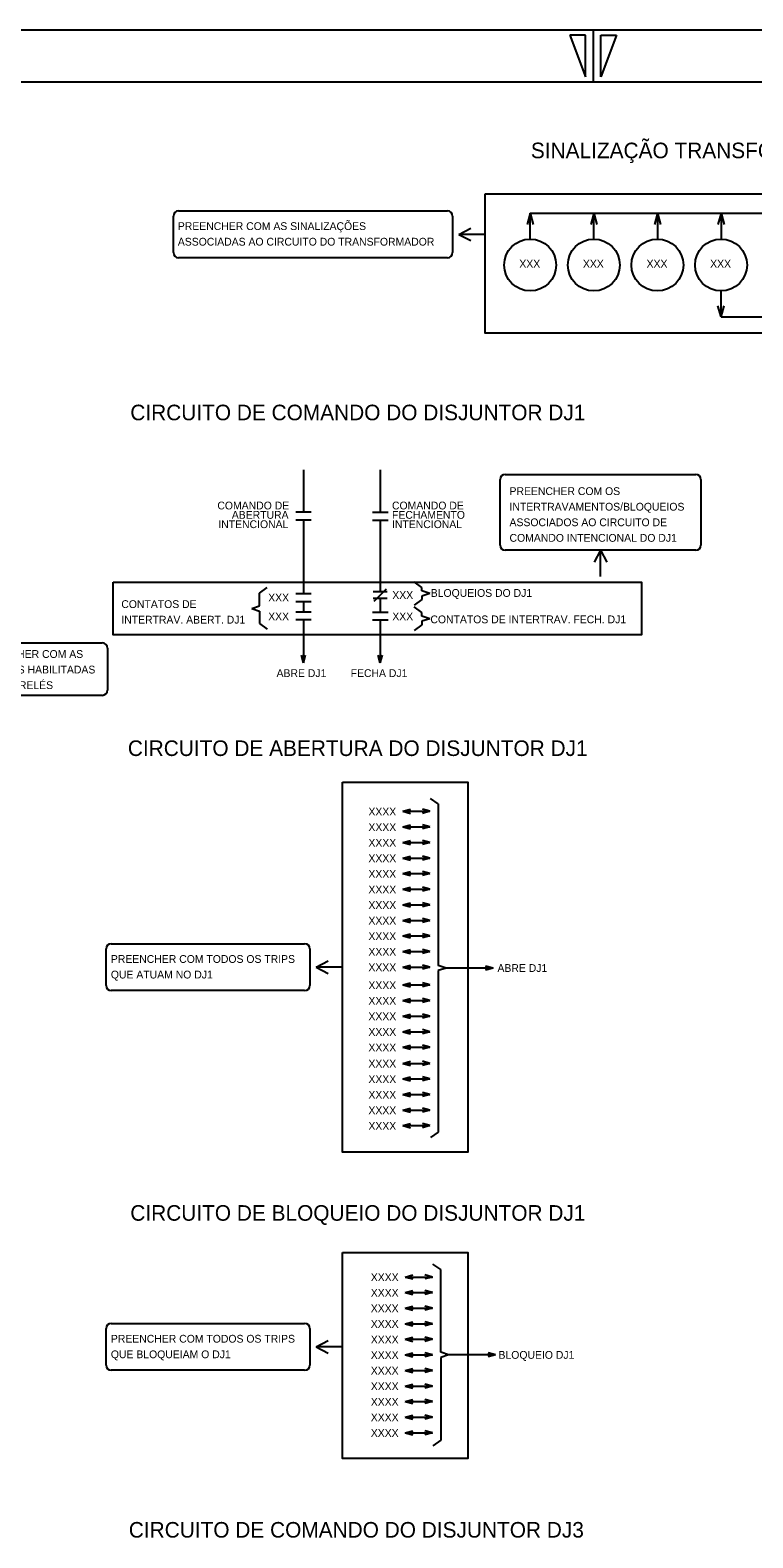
# Model space of a CAD drawing. Extents: x 501 to 1404, y 358 to 952.
# Drawn here: x 1110.2 to 1249.3, y 661.6 to 952 of the extents above; entities that cross this region are included whole.
import ezdxf

# ---------------------------------------------------------------- set-up
doc = ezdxf.new("R2010")
doc.units = 0
doc.layers.add('New Level (0)', color=7, linetype='Continuous')

# ---------------------------------------------------------------- blocks, each defined once
blk = doc.blocks.new('39')
for p, q in [((0, 0), (1.45, 0.39)), ((0, 0), (5.22, 0)), ((0, 0), (1.45, -0.39)), ((5.22, 0), (3.77, 0.39)), ((5.22, 0), (3.77, -0.39))]:
    blk.add_line(p, q)

msp = doc.modelspace()

# ---------------------------------------------------------------- linework, layer by layer
for p, q in [((1206.46, 916.72), (1205.87, 914.55)), ((1206.46, 911.72), (1206.46, 916.72)), ((1206.46, 916.72), (1265.58, 916.72)), ((1206.46, 916.72), (1207.04, 914.55)), ((1218.7, 916.72), (1218.12, 914.55)), ((1218.7, 911.72), (1218.7, 916.72)), ((1218.7, 916.72), (1219.28, 914.55)), ((1230.94, 916.72), (1230.36, 914.55)), ((1230.94, 916.72), (1230.94, 911.72)), ((1230.94, 916.72), (1231.53, 914.55)), ((1243.19, 916.72), (1242.6, 914.55)), ((1243.19, 916.72), (1243.19, 911.72)), ((1243.19, 916.72), (1243.77, 914.55)), ((1243.19, 896.72), (1243.19, 901.72)), ((1243.19, 896.72), (1242.6, 898.89)), ((1243.19, 896.72), (1243.77, 898.89)), ((1243.19, 896.72), (1265.58, 896.72)), ((1162.82, 867.28), (1162.82, 859.1)), ((1177.61, 867.28), (1177.61, 859.1)), ((1164.32, 859.1), (1161.32, 859.1)), ((1164.32, 857.6), (1161.32, 857.6)), ((1162.82, 857.6), (1162.82, 843.36)), ((1176.11, 859.1), (1179.11, 859.1)), ((1176.11, 857.6), (1179.11, 857.6)), ((1177.61, 857.6), (1177.61, 843.86)), ((1185.62, 844.64), (1184.12, 845.72)), ((1154.36, 843.55), (1155.86, 844.63)), ((1154.36, 841.08), (1154.36, 843.55)), ((1164.32, 843.36), (1161.32, 843.36)), ((1176.26, 843.86), (1178.96, 843.86)), ((1178.96, 842.51), (1176.26, 842.51)), ((1176.42, 842), (1178.8, 844.38)), ((1177.61, 842.36), (1177.61, 839.86)), ((1185.62, 842.27), (1184.12, 841.19)), ((1185.62, 843.96), (1185.62, 844.64)), ((1187.12, 843.46), (1185.62, 843.96)), ((1187.12, 843.46), (1185.62, 842.96)), ((1185.62, 842.96), (1185.62, 842.27)), ((1152.86, 840.58), (1154.36, 841.08)), ((1152.86, 840.58), (1154.36, 840.08)), ((1154.36, 840.08), (1154.36, 837.68)), ((1164.32, 841.86), (1161.32, 841.86)), ((1164.32, 839.86), (1161.32, 839.86)), ((1162.82, 841.86), (1162.82, 839.86)), ((1176.11, 839.86), (1179.11, 839.86)), ((1176.11, 839.86), (1179.11, 839.86)), ((1185.62, 839.78), (1184.12, 840.87)), ((1185.62, 839.1), (1185.62, 839.78)), ((1154.36, 837.68), (1155.86, 836.6)), ((1164.32, 838.36), (1161.32, 838.36)), ((1162.82, 838.36), (1162.82, 830.12)), ((1176.11, 838.36), (1179.11, 838.36)), ((1176.11, 838.36), (1179.11, 838.36)), ((1177.61, 838.36), (1177.61, 830.12)), ((1185.62, 837.42), (1184.12, 836.33)), ((1187.12, 838.6), (1185.62, 839.1)), ((1187.12, 838.6), (1185.62, 838.1)), ((1185.62, 838.1), (1185.62, 837.42)), ((1162.82, 830.12), (1162.43, 831.57)), ((1162.82, 830.12), (1163.21, 831.57)), ((1177.61, 830.12), (1177.22, 831.57)), ((1177.61, 830.12), (1178, 831.57)), ((1181.94, 801.5), (1183.39, 801.89)), ((1181.94, 801.5), (1187.16, 801.5)), ((1181.94, 801.5), (1183.39, 801.11)), ((1187.16, 801.5), (1185.71, 801.89)), ((1187.16, 801.5), (1185.71, 801.11)), ((1188.76, 802.92), (1187.26, 804)), ((1188.76, 802.92), (1188.76, 771.82)), ((1181.94, 798.5), (1183.39, 798.89)), ((1187.16, 798.5), (1185.71, 798.89)), ((1181.94, 798.5), (1187.16, 798.5)), ((1181.94, 798.5), (1183.39, 798.11)), ((1181.94, 795.5), (1183.39, 795.89)), ((1187.16, 798.5), (1185.71, 798.11)), ((1187.16, 795.5), (1185.71, 795.89)), ((1181.94, 795.5), (1187.16, 795.5)), ((1181.94, 795.5), (1183.39, 795.11)), ((1187.16, 795.5), (1185.71, 795.11)), ((1190.26, 771.32), (1188.76, 771.82)), ((1190.26, 771.32), (1188.76, 770.82)), ((1188.76, 770.82), (1188.76, 739.73)), ((1199.32, 771.32), (1190.26, 771.32)), ((1199.32, 771.32), (1197.87, 771.71)), ((1199.32, 771.32), (1197.87, 770.94)), ((1181.94, 768.06), (1183.39, 768.44)), ((1181.94, 768.06), (1187.16, 768.06)), ((1181.94, 768.06), (1183.39, 767.67)), ((1187.16, 768.06), (1185.71, 768.44)), ((1187.16, 768.06), (1185.71, 767.67)), ((1181.94, 752.96), (1183.39, 753.35)), ((1181.94, 752.96), (1187.16, 752.96)), ((1181.94, 752.96), (1183.39, 752.57)), ((1187.16, 752.96), (1185.71, 753.35)), ((1187.16, 752.96), (1185.71, 752.57)), ((1188.76, 739.73), (1187.26, 738.65)), ((1182.41, 711.81), (1183.86, 712.2)), ((1182.41, 711.81), (1187.63, 711.81)), ((1182.41, 711.81), (1183.86, 711.43)), ((1187.63, 711.81), (1186.18, 712.2)), ((1187.63, 711.81), (1186.18, 711.43)), ((1189.23, 713.23), (1187.73, 714.31)), ((1189.23, 697.31), (1189.23, 713.23)), ((1182.41, 705.81), (1183.86, 706.2)), ((1182.41, 705.81), (1187.63, 705.81)), ((1182.41, 705.81), (1183.86, 705.43)), ((1187.63, 705.81), (1186.18, 706.2)), ((1187.63, 705.81), (1186.18, 705.43)), ((1190.73, 696.81), (1189.23, 697.31)), ((1199.79, 696.81), (1198.34, 697.2)), ((1190.73, 696.81), (1189.23, 696.31)), ((1189.23, 696.31), (1189.23, 680.4)), ((1199.79, 696.81), (1190.73, 696.81)), ((1199.79, 696.81), (1198.34, 696.43)), ((1189.23, 680.4), (1187.73, 679.31))]:
    msp.add_line(p, q)
for centre in [(1206.46, 906.72), (1218.7, 906.72), (1230.94, 906.72), (1243.19, 906.72)]:
    msp.add_circle(centre, 5)
at = {"layer": 'New Level (0)'}
for p, q in [((1403.58, 951.96), (562.58, 951.96)), ((1403.58, 951.96), (562.58, 951.96)), ((1217.08, 950.96), (1214.08, 950.96)), ((1214.08, 950.96), (1217.08, 942.96)), ((1217.08, 942.96), (1217.08, 950.96)), ((1218.58, 951.96), (1218.58, 941.96)), ((1220.08, 942.96), (1220.08, 950.96)), ((1220.08, 950.96), (1223.08, 950.96)), ((1223.08, 950.96), (1220.08, 942.96)), ((1393.58, 941.96), (572.58, 941.96)), ((1137.78, 909.11), (1137.78, 916.14)), ((1138.78, 917.14), (1160.63, 917.14)), ((1160.63, 917.14), (1190.51, 917.14)), ((1191.51, 916.14), (1191.51, 909.11)), ((1192.74, 912.63), (1195.04, 913.84)), ((1197.77, 912.63), (1192.74, 912.63)), ((1192.74, 912.63), (1195.04, 911.42)), ((1190.51, 908.11), (1138.78, 908.11)), ((1200.66, 852.79), (1200.66, 865.38)), ((1201.66, 866.38), (1238.32, 866.38)), ((1239.32, 865.38), (1239.32, 852.79)), ((1238.32, 851.79), (1201.66, 851.79)), ((1219.99, 851.79), (1218.78, 849.49)), ((1219.99, 846.76), (1219.99, 851.79)), ((1219.99, 851.79), (1221.2, 849.49)), ((1106.43, 833.95), (1124.09, 833.95)), ((1125.09, 832.95), (1125.09, 824.84)), ((1124.09, 823.84), (1099.08, 823.84)), ((1125.82, 776.01), (1133.17, 776.01)), ((1133.17, 776.01), (1163.05, 776.01)), ((1124.82, 767.98), (1124.82, 775.01)), ((1164.05, 775.01), (1164.05, 767.98)), ((1165.29, 771.5), (1167.58, 772.71)), ((1170.32, 771.5), (1165.29, 771.5)), ((1165.29, 771.5), (1167.58, 770.29)), ((1163.05, 766.98), (1125.82, 766.98)), ((1125.82, 702.87), (1133.17, 702.87)), ((1133.17, 702.87), (1163.05, 702.87)), ((1124.82, 694.84), (1124.82, 701.87)), ((1164.05, 701.87), (1164.05, 694.84)), ((1165.29, 698.36), (1167.58, 699.57)), ((1170.32, 698.36), (1165.29, 698.36)), ((1165.29, 698.36), (1167.58, 697.15)), ((1163.05, 693.84), (1125.82, 693.84))]:
    msp.add_line(p, q, dxfattribs=at)
for points in [[(1197.77, 920.41), (1261.69, 920.41), (1261.69, 893.59), (1197.77, 893.59)], [(1126.19, 845.66), (1227.89, 845.66), (1227.89, 835.49), (1126.19, 835.49)], [(1170.32, 807.12), (1194.45, 807.12), (1194.45, 735.87), (1170.32, 735.87)], [(1170.32, 716.5), (1194.45, 716.5), (1194.45, 676.86), (1170.32, 676.86)]]:
    msp.add_lwpolyline(points, close=True, dxfattribs=at)
for centre, start, end in [((1138.78, 916.14), 90, 180), ((1190.51, 916.14), 0, 90), ((1138.78, 909.11), 180, 270), ((1190.51, 909.11), 270, 0), ((1201.66, 865.38), 90, 180), ((1238.32, 865.38), 0, 90), ((1201.66, 852.79), 180, 270), ((1238.32, 852.79), 270, 0), ((1124.09, 832.95), 0, 90), ((1124.09, 824.84), 270, 0), ((1125.82, 775.01), 90, 180), ((1163.05, 775.01), 0, 90), ((1125.82, 767.98), 180, 270), ((1163.05, 767.98), 270, 0), ((1125.82, 701.87), 90, 180), ((1163.05, 701.87), 0, 90), ((1125.82, 694.84), 180, 270), ((1163.05, 694.84), 270, 0)]:
    msp.add_arc(centre, 1, start, end, dxfattribs=at)

# ---------------------------------------------------------------- block references
for p in [(1181.94, 792.5), (1181.94, 789.5), (1181.94, 786.5), (1181.94, 783.5), (1181.94, 780.5), (1181.94, 777.5), (1181.94, 774.5), (1181.94, 771.5), (1181.94, 765.06), (1181.94, 762.06), (1181.94, 759.06), (1181.94, 756.06), (1181.94, 749.96), (1181.94, 746.96), (1181.94, 743.96), (1181.94, 740.96), (1182.41, 708.81), (1182.41, 702.81), (1182.41, 699.81), (1182.41, 696.81), (1182.41, 693.81), (1182.41, 690.81), (1182.41, 687.81), (1182.41, 684.81), (1182.41, 681.81)]:
    msp.add_blockref('39', p)

# ---------------------------------------------------------------- texts
for s, height, p in [('SINALIZAÇÃO TRANSFORMADOR T1', 3, (1206.59, 927.29)), ('PREENCHER COM AS SINALIZAÇÕES', 1.5, (1138.64, 913.46)), ('ASSOCIADAS AO CIRCUITO DO TRANSFORMADOR', 1.5, (1138.64, 910.46)), ('XXX', 1.5, (1204.37, 906.22)), ('XXX', 1.5, (1216.61, 906.22)), ('XXX', 1.5, (1228.86, 906.22)), ('XXX', 1.5, (1241.1, 906.22)), ('CIRCUITO DE COMANDO DO DISJUNTOR DJ1', 3, (1129.49, 876.82)), ('PREENCHER COM OS ', 1.5, (1202.48, 862.42)), ('COMANDO DE', 1.5, (1146.25, 859.65)), ('COMANDO DE ', 1.5, (1179.86, 859.65)), ('INTERTRAVAMENTOS/BLOQUEIOS', 1.5, (1202.48, 859.42)), (' INTENCIONAL', 1.5, (1145.87, 856.05)), (' ABERTURA', 1.5, (1148.47, 857.85)), ('FECHAMENTO ', 1.5, (1179.86, 857.85)), ('INTENCIONAL', 1.5, (1179.86, 856.05)), ('ASSOCIADOS AO CIRCUITO DE ', 1.5, (1202.48, 856.42)), ('COMANDO INTENCIONAL DO DJ1', 1.5, (1202.48, 853.42)), ('CONTATOS DE ', 1.5, (1127.76, 840.66)), ('XXX', 1.5, (1156.03, 841.92)), ('XXX', 1.5, (1179.92, 842.41)), ('BLOQUEIOS DO DJ1', 1.5, (1187.32, 842.81)), ('XXX', 1.5, (1156.03, 838.29)), ('XXX', 1.5, (1179.92, 838.29)), ('CONTATOS DE INTERTRAV. FECH. DJ1', 1.5, (1187.25, 837.72)), ('INTERTRAV. ABERT. DJ1', 1.5, (1127.76, 837.66)), ('PREENCHER COM AS ', 1.5, (1099.35, 831.05)), ('FUNÇÕES HABILITADAS ', 1.5, (1099.35, 828.05)), ('ABRE DJ1', 1.5, (1157.64, 827.37)), ('FECHA DJ1', 1.5, (1171.9, 827.37)), ('NESSES RELÉS', 1.5, (1099.35, 825.05)), ('CIRCUITO DE ABERTURA DO DISJUNTOR DJ1', 3, (1129.02, 812.16)), ('XXXX', 1.5, (1175.32, 800.7)), ('XXXX', 1.5, (1175.32, 797.7)), ('XXXX', 1.5, (1175.32, 794.7)), ('XXXX', 1.5, (1175.32, 791.7)), ('XXXX', 1.5, (1175.32, 788.7)), ('XXXX', 1.5, (1175.32, 785.7)), ('XXXX', 1.5, (1175.32, 782.7)), ('XXXX', 1.5, (1175.32, 779.7)), ('XXXX', 1.5, (1175.32, 776.7)), ('PREENCHER COM TODOS OS TRIPS', 1.5, (1125.75, 772.31)), ('XXXX', 1.5, (1175.32, 773.7)), ('QUE ATUAM NO DJ1', 1.5, (1125.75, 769.31)), ('XXXX', 1.5, (1175.32, 770.7)), ('ABRE DJ1', 1.5, (1200.16, 770.57)), ('XXXX', 1.5, (1175.32, 767.26)), ('XXXX', 1.5, (1175.32, 764.26)), ('XXXX', 1.5, (1175.32, 761.26)), ('XXXX', 1.5, (1175.32, 758.26)), ('XXXX', 1.5, (1175.32, 755.26)), ('XXXX', 1.5, (1175.32, 752.16)), ('XXXX', 1.5, (1175.32, 749.16)), ('XXXX', 1.5, (1175.32, 746.16)), ('XXXX', 1.5, (1175.32, 743.16)), ('XXXX', 1.5, (1175.32, 740.16)), ('CIRCUITO DE BLOQUEIO DO DISJUNTOR DJ1', 3, (1129.49, 722.65)), ('XXXX', 1.5, (1175.78, 711.02)), ('XXXX', 1.5, (1175.78, 708.02)), ('XXXX', 1.5, (1175.78, 705.02)), ('XXXX', 1.5, (1175.78, 702.02)), ('PREENCHER COM TODOS OS TRIPS', 1.5, (1125.75, 699.17)), ('XXXX', 1.5, (1175.78, 699.02)), ('QUE BLOQUEIAM O DJ1', 1.5, (1125.75, 696.17)), ('XXXX', 1.5, (1175.78, 696.02)), ('BLOQUEIO DJ1', 1.5, (1200.36, 696.06)), ('XXXX', 1.5, (1175.78, 693.02)), ('XXXX', 1.5, (1175.78, 690.02)), ('XXXX', 1.5, (1175.78, 687.02)), ('XXXX', 1.5, (1175.78, 684.02)), ('XXXX', 1.5, (1175.78, 681.02)), ('CIRCUITO DE COMANDO DO DISJUNTOR DJ3', 3, (1129.2, 661.62))]:
    msp.add_text(s, height=height).set_placement(p)

doc.saveas('drawing.dxf')
